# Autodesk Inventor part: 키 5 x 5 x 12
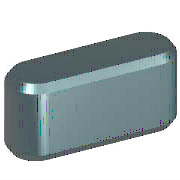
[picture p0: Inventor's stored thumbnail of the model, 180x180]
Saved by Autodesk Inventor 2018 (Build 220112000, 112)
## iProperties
Created: 2012-02
Part Number: 키 5 x 5 x 12
Material: 강철, 연강
Description: 키 및 해당 키홈
Document SubType Name: Modeling
Standard: KS B 1311
Designer: mduedu
Standards Organization: KS
Language: ko-KR
Size Designation: 5 x 5 x 12
Categories: <MemberInstance><Categories><Category DisplayName="샤프트 부품" InternalName="7f7aeb1f-a693-4053-b835-cee3144e0d98" Mnemonic="SHFT"><Category DisplayName="키" Interna
Density: 1 g/cm^3
Appearance: 노란색
IsCustomPart: 1
Author: mduedu
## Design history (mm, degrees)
workplane "Work Plane1"
workplane "Work Plane2"
sketch "스케치1"
  geometry: L1 (2.5, 2.5)-(9.5, 2.5); L2 (9.5, -2.5)-(2.5, -2.5); L3 (0, 9.4)-(0, -7.4) reference; L4 (-5, 0)-(30, 0) reference; L5 (12, 0)-(12, 7); A1 r 2.5 centre (2.5, 0) between (2.5, 2.5) and (2.5, -2.5); A2 r 2.5 centre (9.5, 0) between (9.5, -2.5) and (9.5, 2.5)
  constraints: 6 end point, 5 point on circle, 4 tangent, 3 point on line, 2 centre point, 1 horizontal, 1 parallel, 1 perpendicular
  dimensions: "d0" = 2.5 radius of A1 (= 0.5 x PB); "d13" = 2.5 radius of A2 (= 0.5 x PB); "d14" = 12 distance between parallel lines of L5 L3 (= NLG)
extrude "본체1" new body sketch "스케치1" taper "d3" = 0 deg; stored distance "d4" = 10
workplane "Work Plane3"
body "Solid1"
chamfer "모따기1" distance "d8" = 0.4 (= PHH); stored, may be unused: second distance "d9" = 0.4 (= PHH), angle "d15" = 45 deg
other parameters: "d1" = -3 (= -PNT), "d2" = 2 (= PH - PNT), "NLG" = 12 [user parameter; used in 3 equation terms], "PB" = 5 [user parameter; used in 2 equation terms], "PNT" = 3 [user parameter; used in 2 equation terms], "PH" = 5 [user parameter; used in 1 equation term], "PHH" = 0.4 [user parameter; used in 2 equation terms], "d10" = 0, "d16" = 0, "d17" = 0, "d18" = 0, "WDMIN" = 12 [user parameter], "PLB2" = 12 (= NLG) [user parameter], "WDMAX" = 17 [user parameter], "PLB1" = 12 (= NLG) [user parameter], "RR" = 0.16 [user parameter], "PUEB" = 2.3 [user parameter]
